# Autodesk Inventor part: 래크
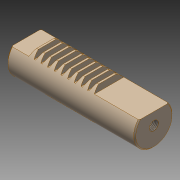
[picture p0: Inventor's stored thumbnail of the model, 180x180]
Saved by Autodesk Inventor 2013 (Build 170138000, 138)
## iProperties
Created: 2019-06
Part Number: 래크
Material: 스테인리스강
Document SubType Name: Modeling
Designer: mduedu
Density: 1 g/cm^3
Author: mduedu
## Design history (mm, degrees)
sketch "스케치1"
  geometry: L1 (0, 0)-(120, 0); L2 (120, 0)-(120, 34); L3 (120, 34)-(0, 34); L4 (0, 34)-(0, 0)
  constraints: 8 end point, 2 parallel, 1 horizontal, 1 perpendicular
  dimensions: "d0" = 120 distance of L1.start L1.end; "d1" = 34 distance of L1.end L2.end
extrude "돌출1" new body sketch "스케치1" stored distance "d2" = 36; taper "d3" = 0 deg
sketch "스케치2"
  geometry: L1 (0, 0)-(120, 0) reference; L2 (120, 0)-(120, 34) reference; L3 (120, 34)-(0, 34) reference; L4 (0, 34)-(0, 0) reference; L5 (15.1, 29.5)-(16.42, 29.5); L6 (18.058, 34)-(13.462, 34); L7 (15.76, 34)-(15.76, 29.5); L8 (13.462, 34)-(15.1, 29.5); L9 (18.058, 34)-(16.42, 29.5); L10 (14.19, 32)-(17.33, 32); 1 further point
  constraints: 12 end point, 2 midpoint, 2 point on line, 1 collinear, 1 horizontal, 1 parallel, 1 perpendicular, 1 symmetric about line
  dimensions: "d4" = 20 deg angle of L9 L7; "d5" = 2 distance between parallel lines of L10 L6; "d7" = 4.5 distance between parallel lines of L5 L6 (= 2.25 x d5); "d8" = 3.14 distance of L10.start L10.end; "d9" = 15.76 distance between parallel lines of L4 L7
extrude "돌출2" cut sketch "스케치2" stored distance "d10" = 36; taper "d11" = 0 deg
sketch "스케치3"
  geometry: L1 (120, 34)-(80.858, 34) reference; L2 (68.298, 34)-(66.66, 29.5) reference; L3 (66.66, 29.5)-(65.34, 29.5) reference; L4 (65.34, 29.5)-(63.702, 34) reference; L5 (62.018, 34)-(60.38, 29.5) reference; L6 (60.38, 29.5)-(59.06, 29.5) reference; L7 (59.06, 29.5)-(57.422, 34) reference; L8 (57.422, 34)-(55.738, 34) reference; L9 (55.738, 34)-(54.1, 29.5) reference; L10 (54.1, 29.5)-(52.78, 29.5) reference; L11 (52.78, 29.5)-(51.142, 34) reference; L12 (51.142, 34)-(49.458, 34) reference; L13 (49.458, 34)-(47.82, 29.5) reference; L14 (47.82, 29.5)-(46.5, 29.5) reference; L15 (46.5, 29.5)-(44.862, 34) reference; L16 (44.862, 34)-(43.178, 34) reference; L17 (43.178, 34)-(41.54, 29.5) reference; L18 (41.54, 29.5)-(40.22, 29.5) reference; L19 (40.22, 29.5)-(38.582, 34) reference; L20 (38.582, 34)-(36.898, 34) reference; L21 (36.898, 34)-(35.26, 29.5) reference; L22 (35.26, 29.5)-(33.94, 29.5) reference; L23 (33.94, 29.5)-(32.302, 34) reference; L24 (32.302, 34)-(30.618, 34) reference; L25 (30.618, 34)-(28.98, 29.5) reference; L26 (28.98, 29.5)-(27.66, 29.5) reference; L27 (27.66, 29.5)-(26.022, 34) reference; L28 (26.022, 34)-(24.338, 34) reference; L29 (24.338, 34)-(22.7, 29.5) reference; L30 (22.7, 29.5)-(21.38, 29.5) reference; L31 (21.38, 29.5)-(19.742, 34) reference; L32 (19.742, 34)-(18.058, 34) reference; L33 (18.058, 34)-(16.42, 29.5) reference; L34 (16.42, 29.5)-(15.1, 29.5) reference; L35 (15.1, 29.5)-(13.462, 34) reference; L36 (0, 34)-(0, 0) reference; L37 (0, 0)-(120, 0) reference; L38 (120, 0)-(120, 34) reference; L39 (13.462, 34)-(0, 34) reference; L40 (80.858, 34)-(79.22, 29.5) reference; L41 (79.22, 29.5)-(77.9, 29.5) reference; L42 (77.9, 29.5)-(76.262, 34) reference; L43 (74.578, 34)-(72.94, 29.5) reference; L44 (72.94, 29.5)-(71.62, 29.5) reference; L45 (71.62, 29.5)-(69.982, 34) reference; L46 (69.982, 34)-(68.298, 34) reference; L47 (63.702, 34)-(62.018, 34) reference; L48 (76.262, 34)-(74.578, 34) reference; L49 (15.1, 29.5)-(0, 29.5); L50 (79.22, 29.5)-(120, 29.5); 1 further point
  constraints: 4 end point, 2 perpendicular, 2 point on line
extrude "돌출3" cut sketch "스케치3" stored distance "d18" = 36; taper "d19" = 0 deg
sketch "스케치4"
  geometry: L1 (0, 29.5)-(0, 0) reference; L2 (0, 0)-(120, 0) reference; L3 (120, 0)-(120, 29.5) reference; L4 (76.262, 34)-(74.578, 34) reference; L5 (68.298, 34)-(66.66, 29.5) reference; L6 (66.66, 29.5)-(65.34, 29.5) reference; L7 (65.34, 29.5)-(63.702, 34) reference; L8 (62.018, 34)-(60.38, 29.5) reference; L9 (60.38, 29.5)-(59.06, 29.5) reference; L10 (59.06, 29.5)-(57.422, 34) reference; L11 (57.422, 34)-(55.738, 34) reference; L12 (55.738, 34)-(54.1, 29.5) reference; L13 (54.1, 29.5)-(52.78, 29.5) reference; L14 (52.78, 29.5)-(51.142, 34) reference; L15 (51.142, 34)-(49.458, 34) reference; L16 (49.458, 34)-(47.82, 29.5) reference; L17 (47.82, 29.5)-(46.5, 29.5) reference; L18 (46.5, 29.5)-(44.862, 34) reference; L19 (44.862, 34)-(43.178, 34) reference; L20 (43.178, 34)-(41.54, 29.5) reference; L21 (41.54, 29.5)-(40.22, 29.5) reference; L22 (40.22, 29.5)-(38.582, 34) reference; L23 (38.582, 34)-(36.898, 34) reference; L24 (36.898, 34)-(35.26, 29.5) reference; L25 (35.26, 29.5)-(33.94, 29.5) reference; L26 (33.94, 29.5)-(32.302, 34) reference; L27 (32.302, 34)-(30.618, 34) reference; L28 (30.618, 34)-(28.98, 29.5) reference; L29 (28.98, 29.5)-(27.66, 29.5) reference; L30 (27.66, 29.5)-(26.022, 34) reference; L31 (26.022, 34)-(24.338, 34) reference; L32 (24.338, 34)-(22.7, 29.5) reference; L33 (22.7, 29.5)-(21.38, 29.5) reference; L34 (21.38, 29.5)-(19.742, 34) reference; L35 (19.742, 34)-(18.058, 34) reference; L36 (18.058, 34)-(16.42, 29.5) reference; L37 (16.42, 29.5)-(0, 29.5) reference; L38 (30, 0)-(76, 0); L39 (76, 0)-(76, 4); L40 (76, 4)-(30, 4); L41 (30, 4)-(30, 0); L42 (120, 29.5)-(77.9, 29.5) reference; L43 (77.9, 29.5)-(76.262, 34) reference; L44 (74.578, 34)-(72.94, 29.5) reference; L45 (72.94, 29.5)-(71.62, 29.5) reference; L46 (71.62, 29.5)-(69.982, 34) reference; L47 (69.982, 34)-(68.298, 34) reference; L48 (63.702, 34)-(62.018, 34) reference; 1 further point
  constraints: 8 end point, 2 parallel, 1 horizontal, 1 perpendicular, 1 point on line
  dimensions: "d20" = 30 distance between parallel lines of L41 L1; "d22" = 46 distance between parallel lines of L39 L41; "d23" = 4 distance between parallel lines of L2 L40
extrude "돌출4" cut sketch "스케치4" stored distance "d24" = 36; taper "d25" = 0 deg
sketch "스케치5"
  geometry: L1 (36, 0)-(0, 0) reference; C1 r 18 at (18, 18); 2 further points
  constraints: 1 centre point, 1 midpoint, 1 tangent, 1 vertical alignment
  dimensions: "d26" = 36 diameter of C1
extrude "돌출5" sketch "스케치5" stored distance "d27" = 36; taper "d28" = 0 deg
chamfer "모따기1" distance "d29" = 1; stored, may be unused: second distance "d30" = 2, angle "d31" = 45 deg
hole "구멍1" diameter "d34" = 8.647; stored, may be unused: countersink angle "d38" = 90 deg, drill point angle "d40" = 118 deg; dims "d32" = 10, "d33" = 10, "d35" = 20, "d36" = 4, "d37" = 2, "d39" = 22
node "솔리드1"
pattern_linear "직사각형 패턴1" dims "d14" = 6.28, "d17" = 6.28
node "투영된 루프1"
node "투영된 루프2"
node "투영된 루프3"
